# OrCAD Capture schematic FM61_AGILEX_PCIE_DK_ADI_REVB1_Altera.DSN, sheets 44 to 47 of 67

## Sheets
44 MAX10 - USB Blaster II -2: size B
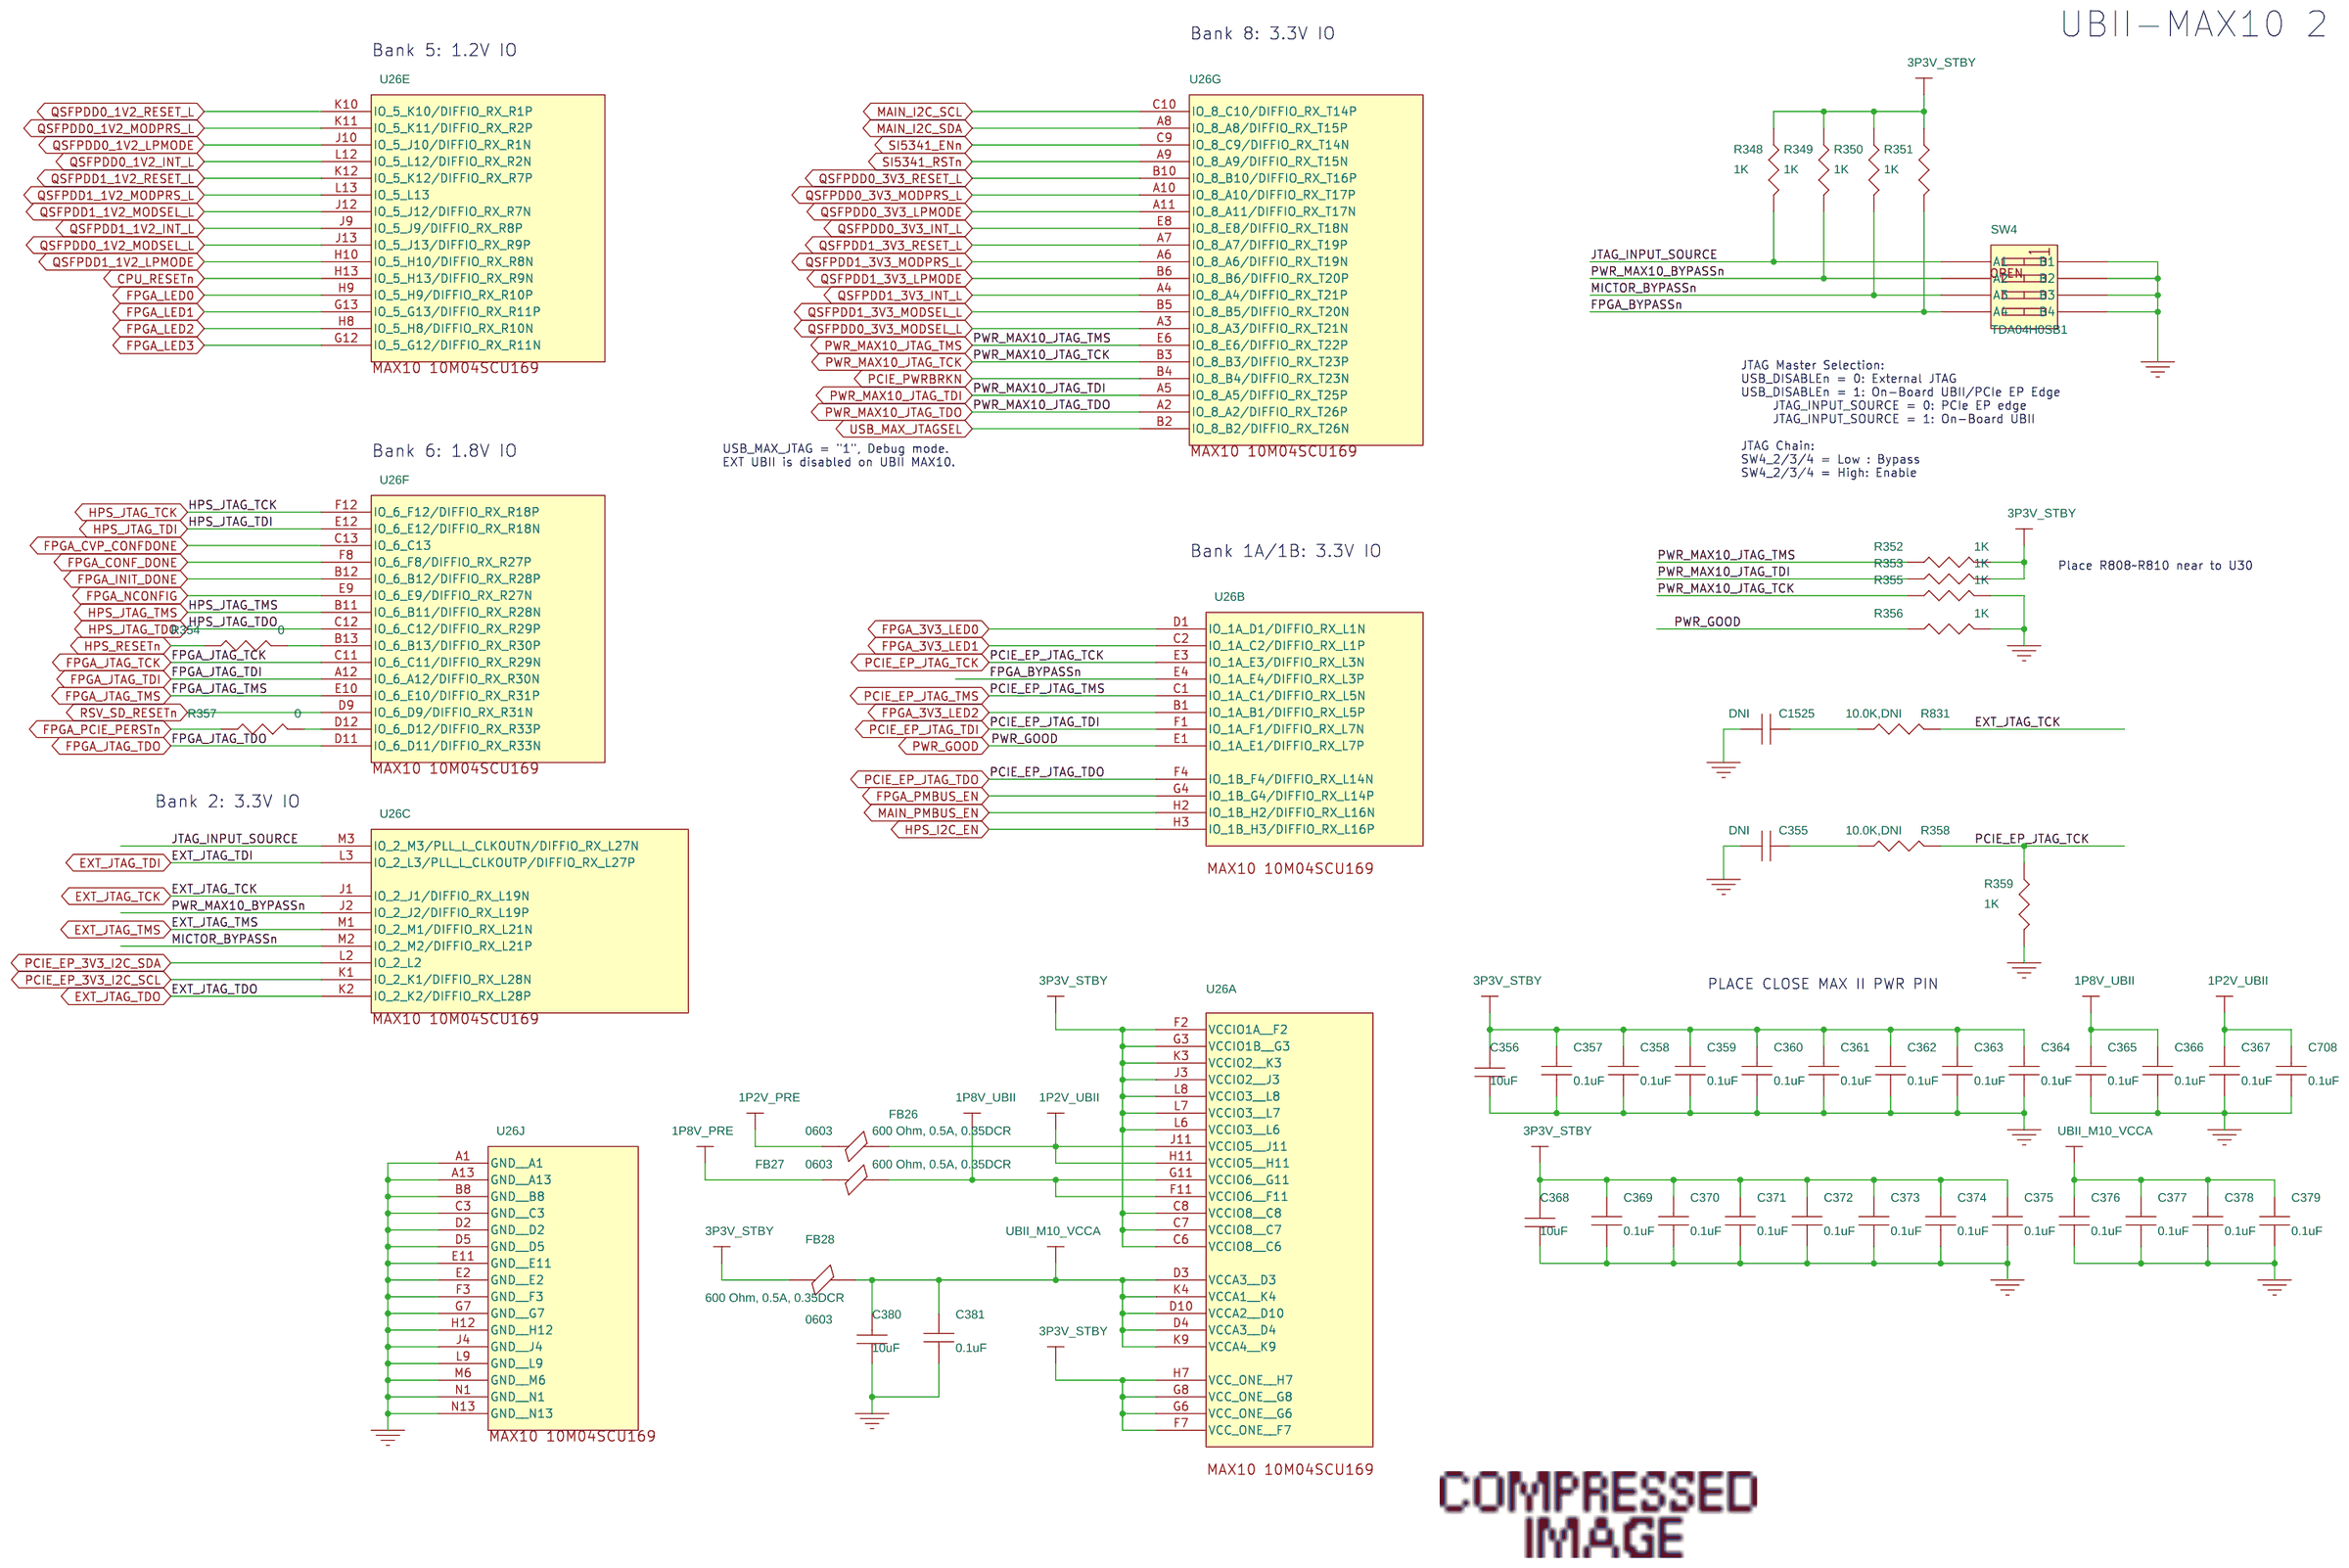
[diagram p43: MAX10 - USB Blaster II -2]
45 PWR - VCCA_PLL: size B
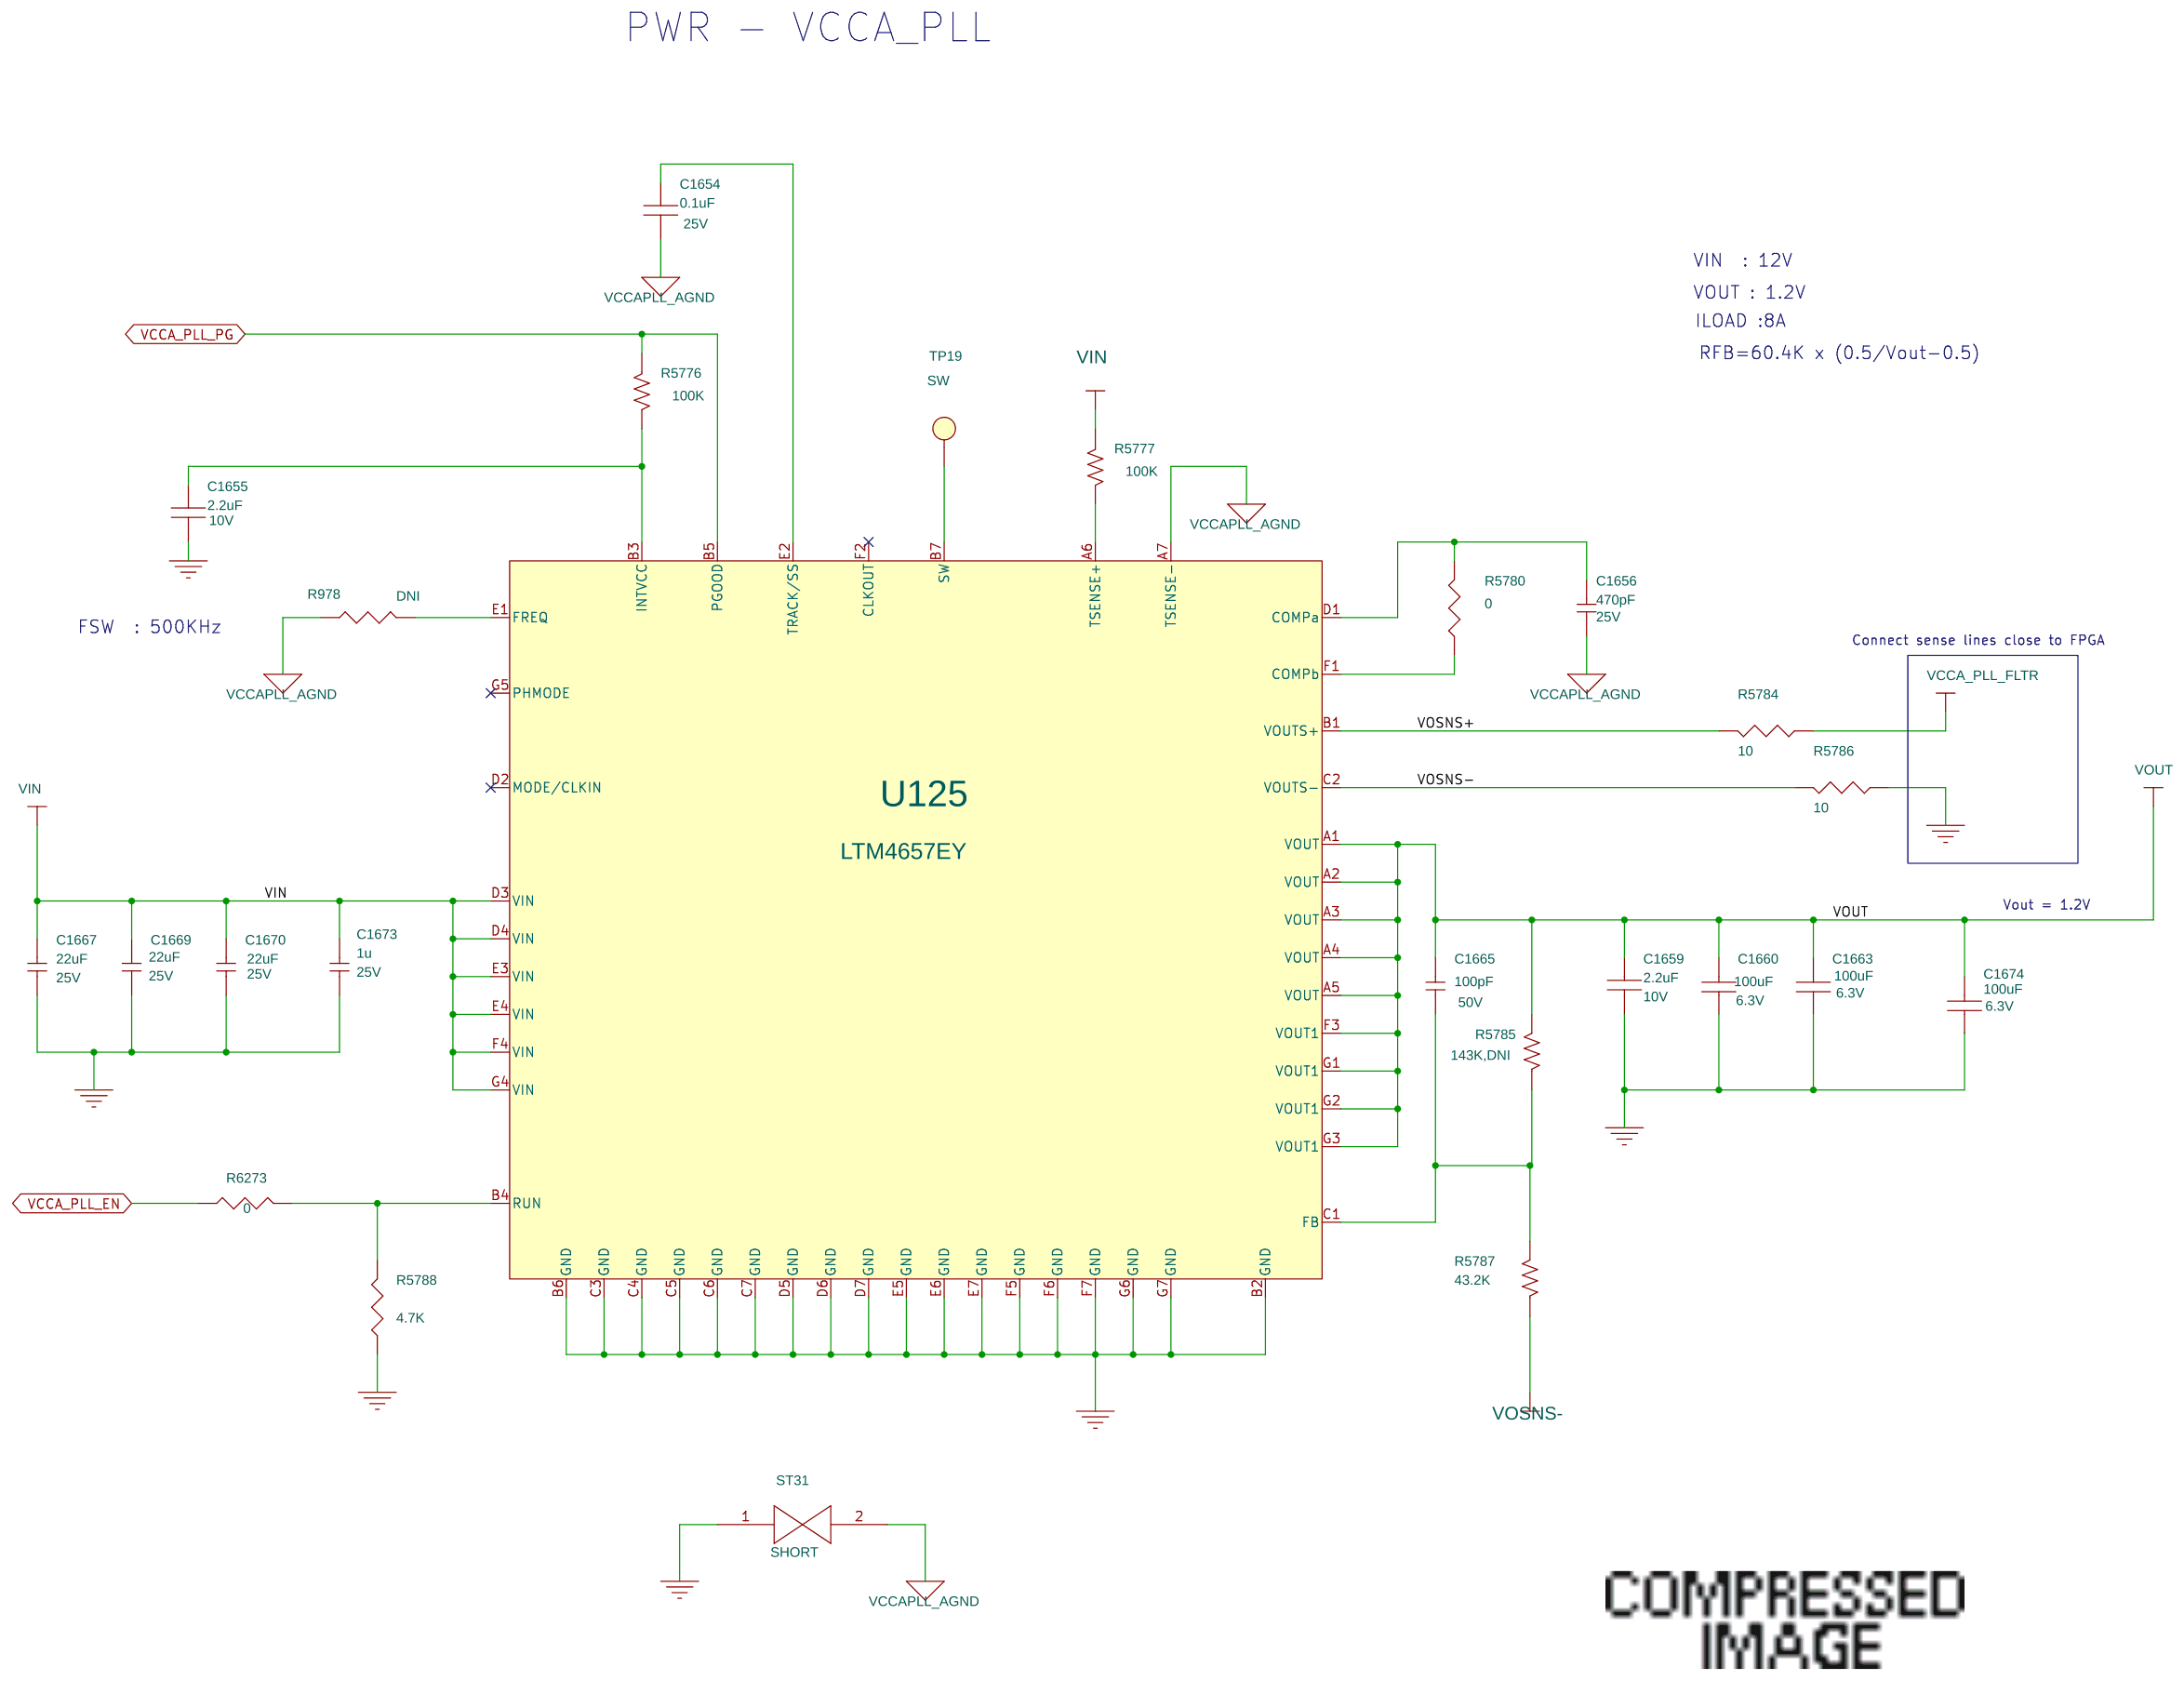
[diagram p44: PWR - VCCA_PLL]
46 MAX10 Power Control -1: size B
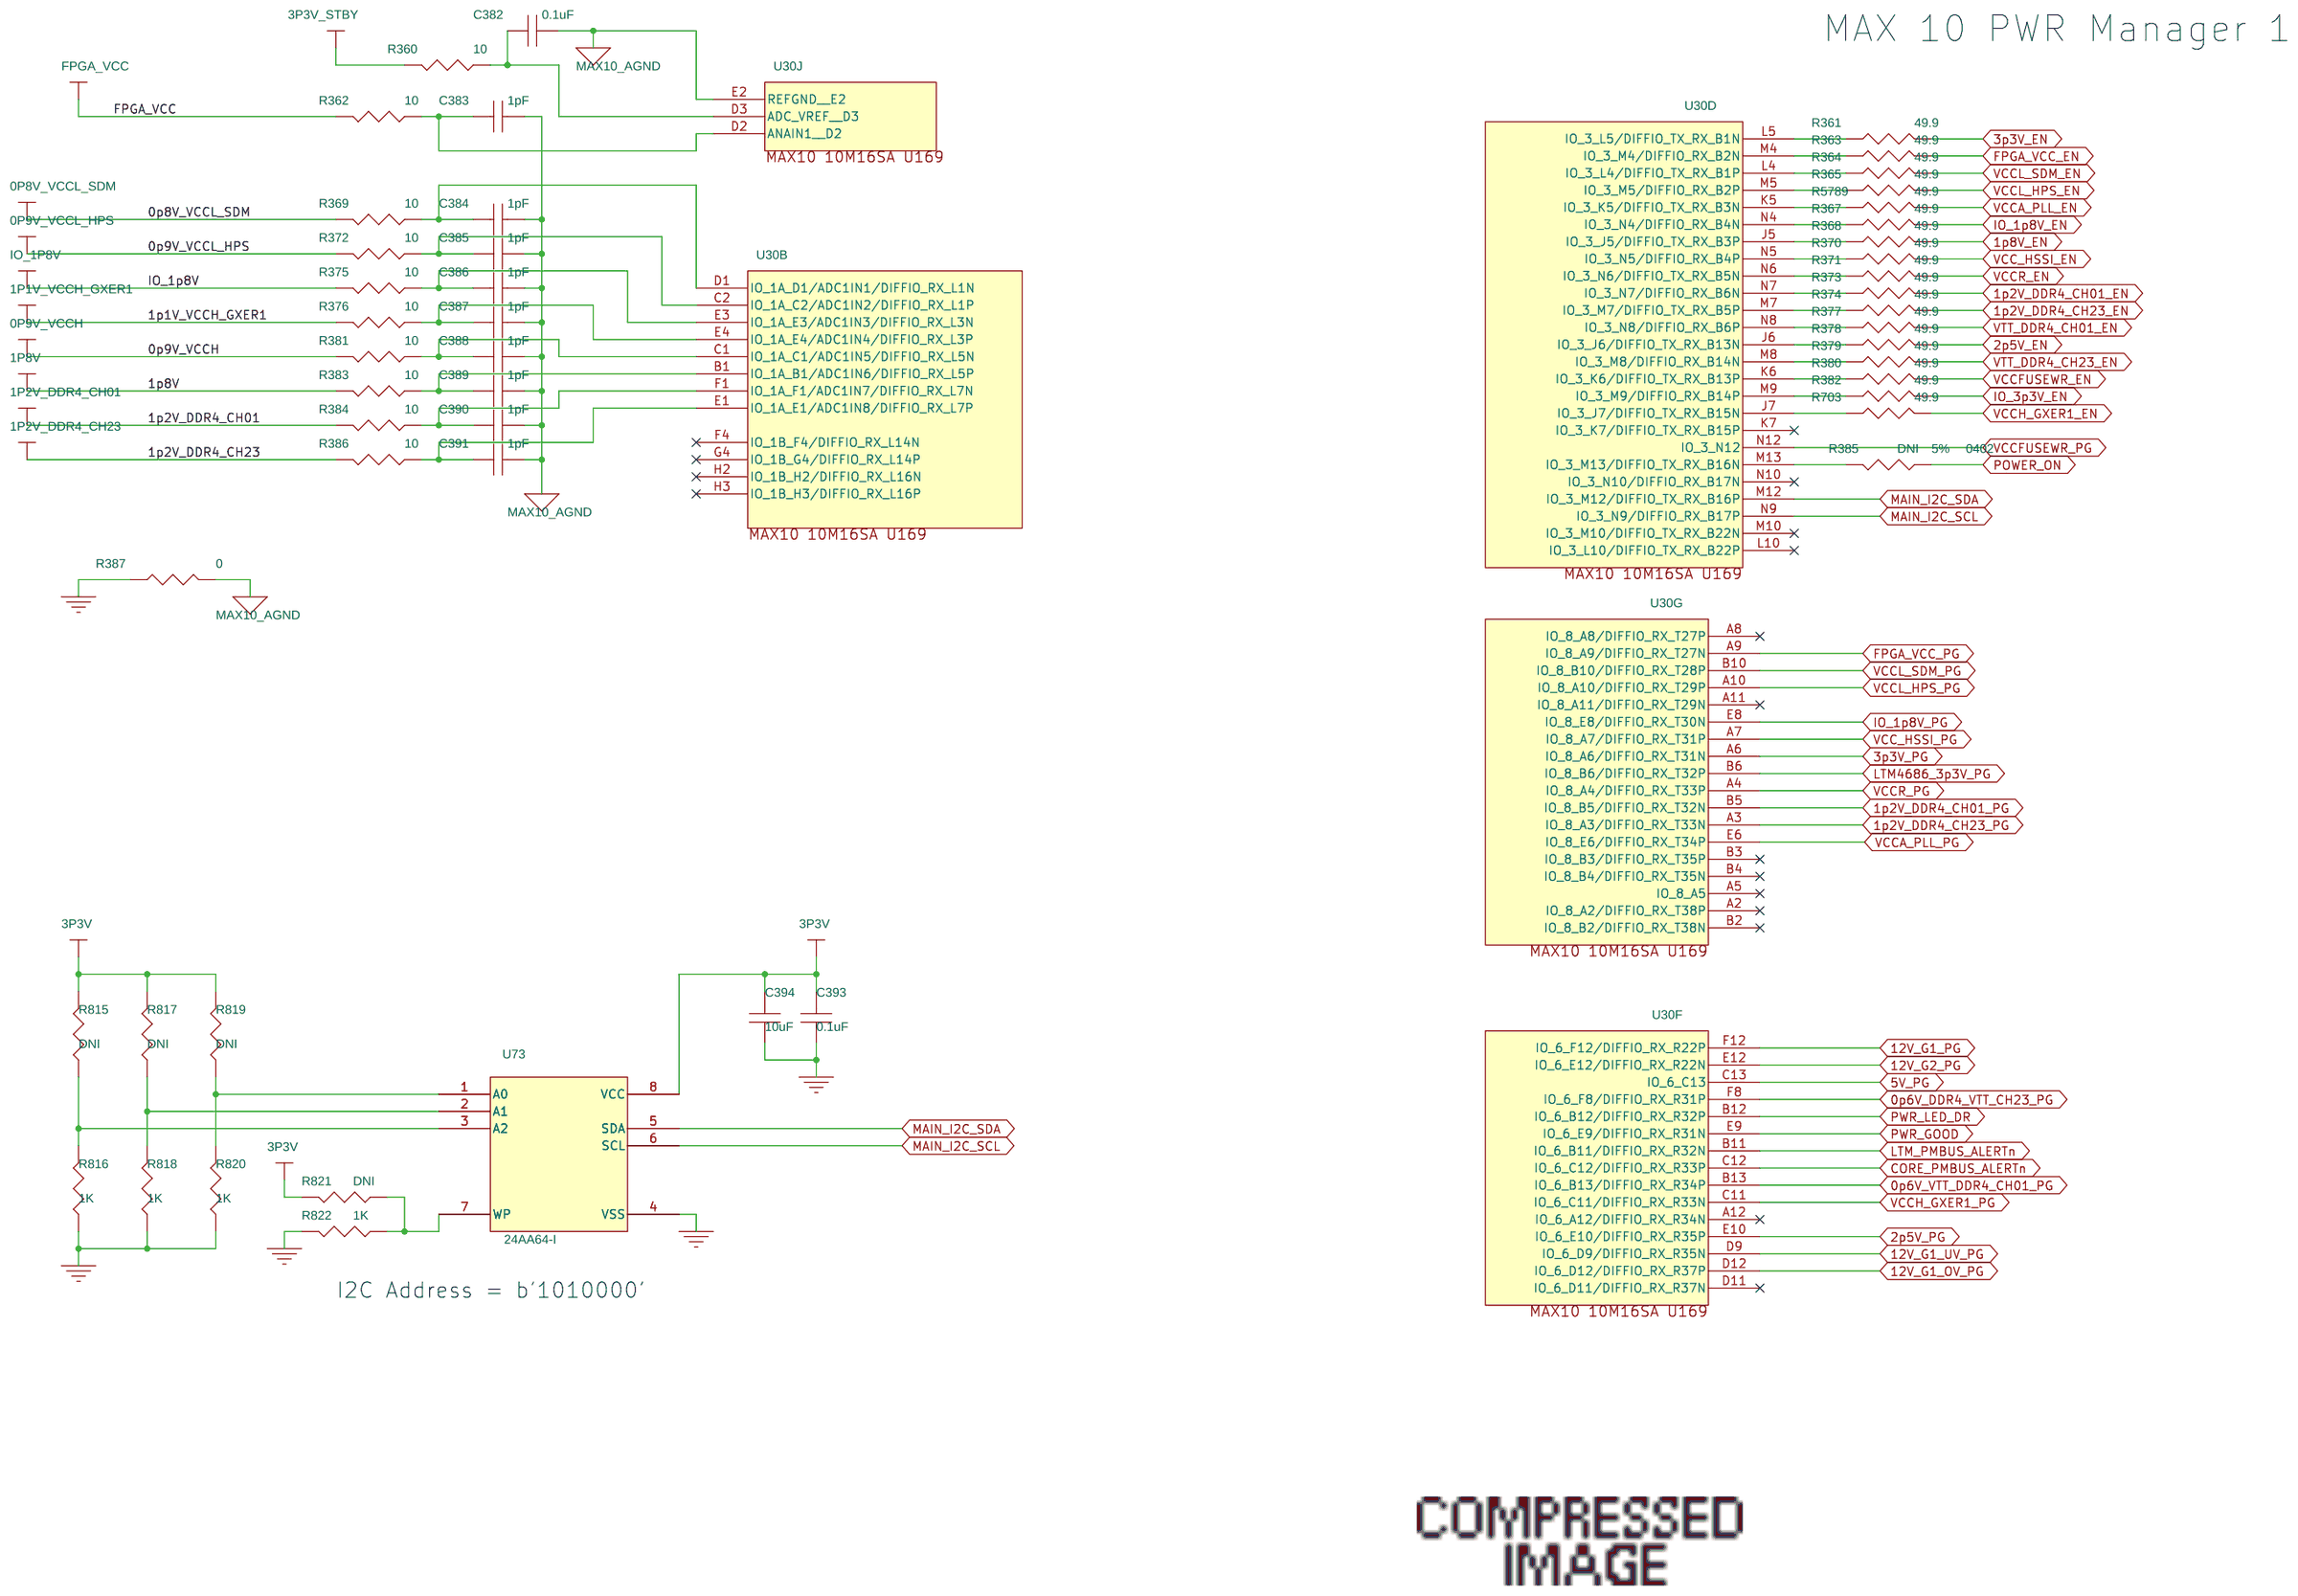
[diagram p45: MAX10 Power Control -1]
47 MAX10 Power Control -2: size B
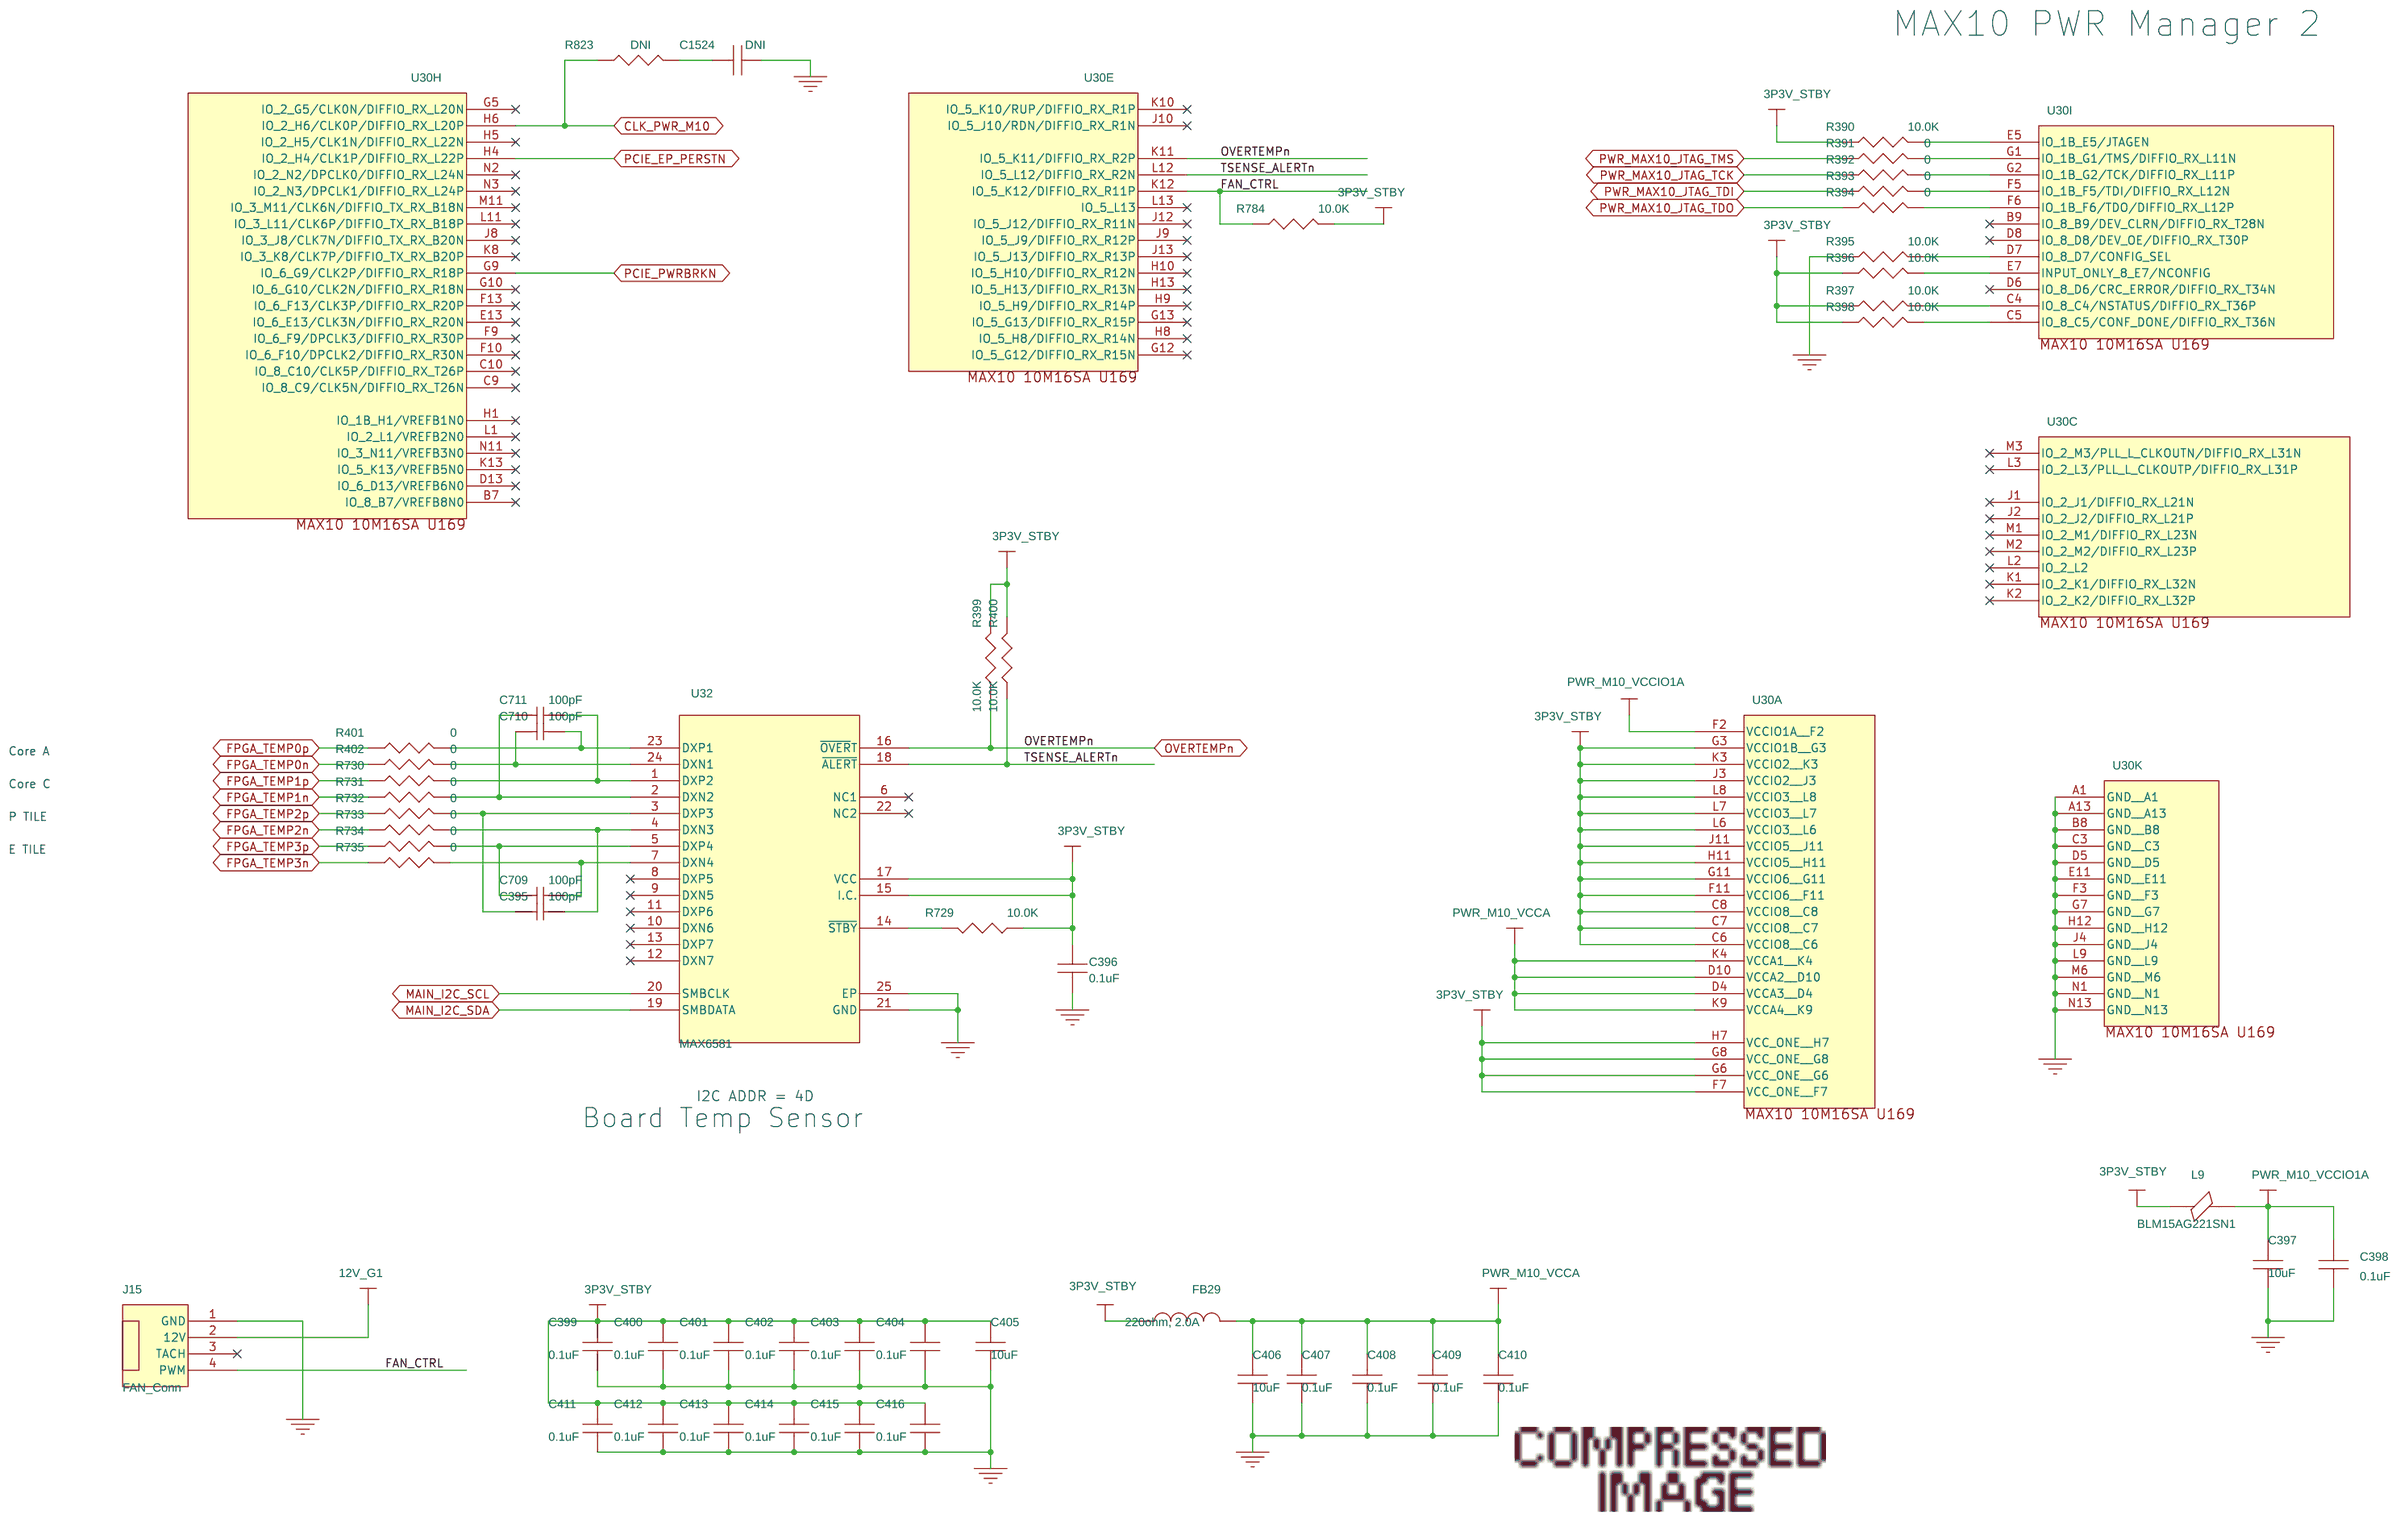
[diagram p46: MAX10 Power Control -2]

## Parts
sheet MAX10 - USB Blaster II -1
U26  10M04SCU169  [BGA169-0R80-11X11]  (sections A,B,C,D,E,F,G,H,I,J)
sheet MAX10 - USB Blaster II -2
C355  DNI  [0402]
C356  10uF  [0603]
C357  0.1uF  [0402]
C358  0.1uF  [0402]
C359  0.1uF  [0402]
C360  0.1uF  [0402]
C361  0.1uF  [0402]
C362  0.1uF  [0402]
C363  0.1uF  [0402]
C364  0.1uF  [0402]
C365  0.1uF  [0402]
C366  0.1uF  [0402]
C367  0.1uF  [0402]
C368  10uF  [0603]
C369  0.1uF  [0402]
C370  0.1uF  [0402]
C371  0.1uF  [0402]
C372  0.1uF  [0402]
C373  0.1uF  [0402]
C374  0.1uF  [0402]
C375  0.1uF  [0402]
C376  0.1uF  [0402]
C377  0.1uF  [0402]
C378  0.1uF  [0402]
C379  0.1uF  [0402]
C380  10uF  [0603]
C381  0.1uF  [0402]
C708  0.1uF  [0402]
C1525  DNI  [0402]
FB26  600 Ohm, 0.5A, 0.35DCR  [0603]
FB27  600 Ohm, 0.5A, 0.35DCR  [0603]
FB28  600 Ohm, 0.5A, 0.35DCR  [0603]
R348  1K  [0402]
R349  1K  [0402]
R350  1K  [0402]
R351  1K  [0402]
R352  1K  [0402]
R353  1K  [0402]
R354  0  [0402]
R355  1K  [0402]
R356  1K  [0402]
R357  0  [0402]
R358  10.0K,DNI  [0402]
R359  1K  [0402]
R831  10.0K,DNI  [0402]
SW4  TDA04H0SB1  [DIPSWITCH_SMT_QUAD]
sheet MAX10 Power Control -1
C382  0.1uF  [0402]
C383  1pF  [0402]
C384  1pF  [0402]
C385  1pF  [0402]
C386  1pF  [0402]
C387  1pF  [0402]
C388  1pF  [0402]
C389  1pF  [0402]
C390  1pF  [0402]
C391  1pF  [0402]
C393  0.1uF  [0402]
C394  10uF  [0603]
R360  10  [0402]
R361  49.9  [0402]
R362  10  [0402]
R363  49.9  [0402]
R364  49.9  [0402]
R365  49.9  [0402]
R367  49.9  [0402]
R368  49.9  [0402]
R369  10  [0402]
R370  49.9  [0402]
R371  49.9  [0402]
R372  10  [0402]
R373  49.9  [0402]
R374  49.9  [0402]
R375  10  [0402]
R376  10  [0402]
R377  49.9  [0402]
R378  49.9  [0402]
R379  49.9  [0402]
R380  49.9  [0402]
R381  10  [0402]
R382  49.9  [0402]
R383  10  [0402]
R384  10  [0402]
R385  DNI  [0402]
R386  10  [0402]
R387  0  [0402]
R703  49.9  [0402]
R815  DNI  [0402]
R816  1K  [0402]
R817  DNI  [0402]
R818  1K  [0402]
R819  DNI  [0402]
R820  1K  [0402]
R821  DNI  [0402]
R822  1K  [0402]
R5789  49.9  [0402]
U30  10M16SA U169_1  [BGA169-0R80-11X11]  (sections A,B,C,D,E,F,G,H,I,J,K)
U73  24AA64-I  [msop8]
sheet MAX10 Power Control -2
C395  100pF  [0402]
C396  0.1uF  [0402]
C397  10uF  [0603]
C398  0.1uF  [0402]
C399  0.1uF  [0402]
C400  0.1uF  [0402]
C401  0.1uF  [0402]
C402  0.1uF  [0402]
C403  0.1uF  [0402]
C404  0.1uF  [0402]
C405  10uF  [0603]
C406  10uF  [0603]
C407  0.1uF  [0402]
C408  0.1uF  [0402]
C409  0.1uF  [0402]
C410  0.1uF  [0402]
C411  0.1uF  [0402]
C412  0.1uF  [0402]
C413  0.1uF  [0402]
C414  0.1uF  [0402]
C415  0.1uF  [0402]
C416  0.1uF  [0402]
C709  100pF  [0402]
C710  100pF  [0402]
C711  100pF  [0402]
C1524  DNI  [0402]
FB29  220ohm, 2.0A  [0805]
J15  FAN_Conn  [Molex_0470533000]
L9  BLM15AG221SN1  [0402]
R390  10.0K  [0402]
R391  0  [0402]
R392  0  [0402]
R393  0  [0402]
R394  0  [0402]
R395  10.0K  [0402]
R396  10.0K  [0402]
R397  10.0K  [0402]
R398  10.0K  [0402]
R399  10.0K  [0402]
R400  10.0K  [0402]
R401  0  [0402]
R402  0  [0402]
R729  10.0K  [0402]
R730  0  [0402]
R731  0  [0402]
R732  0  [0402]
R733  0  [0402]
R734  0  [0402]
R735  0  [0402]
R784  10.0K  [0402]
R823  DNI  [0402]
U32  MAX6581  [24TQFN-EP]
sheet PWR - VCCA_PLL
C1654  0.1uF  [0402]
C1655  2.2uF  [0402]
C1656  470pF  [CAPC1005X60L20L]
C1659  2.2uF  [CC0603N]
C1660  100uF  [1206]
C1663  100uF  [1206]
C1665  100pF  [0402]
C1667  22uF  [1206]
C1669  22uF  [1206]
C1670  22uF  [1206]
C1673  1u  [capc1005x60l20l]
C1674  100uF  [1206]
R978  DNI  [0402]
R5776  100K  [R0402]
R5777  100K  [R0402]
R5780  0  [0402]
R5784  10  [0402]
R5785  143K,DNI  [R0402]
R5786  10  [0402]
R5787  43.2K  [R0402]
R5788  4.7K  [0402]
R6273  0  [0402]
ST31  SHORT  [SHORT]
TP19  TEST PAD  [PADSTYLE1]
U125  LTM4657EY  [LTC-BGA-49-1518]

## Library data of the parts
U26 = 10M04SCU169: IPN: 973665
C355 = CAP: CAPC,Y5V,0402,0.1UF,25V,+80/-20%; Dielectric: Y5V; IPN: K13560-001; Item Num: P03-15057R; Lead Free Status: Yes; Manufacturer: Murata; Manufacturer Part Num: GRM155F51E104ZA01D; Num Pins: 2; Part Class: CAPACITORS; Price: 0.07; RoHS Compliant: Yes; Tolerance: 10%
C356 C368 C380 C394 C397 C405 C406 = CAP: CAP CER 10UF 6.3V X6S 0603; AGILE_LINK: http://sj-agile9app/Agile/PLMServlet?action=OpenEmailObject&classid=10000&objid=257560276; IPN: K19402-001; Item Num: P03-17964R; LIFECYCLE_PHASE: Active; Lead Free Status: Not Lead Free; MFR_LIFECYCLE: Active; Manufacturer: TDK; Manufacturer Part Num: C1608X6S0J106M080AC; Num Pins: 2; PART_SUBCLASS: CAPACITORS; RATED_VOLTAGE: 6.3V; RoHS Compliant: RoHS Compliant; TOLERANCE: 20%; Temperature Coefficient: X6S
C357-C367 C369-C379 C381 C708 = CAP: CAPC,Y5V,0402,0.1UF,25V,+80/-20%; Dielectric: Y5V; IPN: K13560-001; Item Num: P03-15057R; LIFECYCLE_PHASE: Active; Lead Free Status: Lead Free; MFR_LIFECYCLE: Active; Manufacturer: Murata; Manufacturer Part Num: GRM155F51E104ZA01D; Num Pins: 2; PART_SUBCLASS: CAPACITORS; Part Class: CAPACITORS; RATED_VOLTAGE: 25V; RoHS Compliant: RoHS Compliant; Tolerance: +80%/-20%
C1524 C1525 = CAP: CAPC,Y5V,0402,0.1UF,25V,+80/-20%; Dielectric: Y5V; IPN: K13560-001; Item Num: P03-15057R; Lead Free Status: Yes; Manufacturer: Murata; Manufacturer Part Num: GRM155F51E104ZA01D; Num Pins: 2; Part Class: CAPACITORS; Price: 0.07; RATED_VOLTAGE: 25V; RoHS Compliant: Yes; Tolerance: 10%
FB26-FB28 = BEAD_FERRITE_SM: FERRITE BEAD 600 OHM, 0.5A, 0.35 DCR, 0603 1LN; IPN: G73133-001; Item Num: P04-17224R; LIFECYCLE_PHASE: Active; MFR_LIFECYCLE: Active; Manufacturer: Murata; Manufacturer Part Num: BLM18EG601SN1D; Num Pins: 2; Part Class: Inductors; RoHS Compliant: Yes
R348-R353 R355 R356 R359 R815-R822 = RESISTOR: RES,1.00K OHMS,1.0%,1/16W,0402; IPN: G60609-021; Item Num: P02-11372R; Lead Free Status: No; Manufacturer: Panasonic; Manufacturer Part Num: ERJ-2RKF1001X; Num Pins: 2; Part Class: Resistors
R354 R357 R387 R391-R394 R401 R402 R730-R735 = RESISTOR: RES ZERO OHM 1/16W 5% 0402 SMD; Altera Part No.: P02-14020R; IPN: H30887-001; Item Num: P02-14020R; Lead Free Status: No; Manufacturer: Panasonic; Manufacturer Part Num: ERJ-2GE0R00X; Num Pins: 2; Part Class: RESISTORS; RoHS Compliant: Yes; Tolerance: 5%
R358 R831 = RESISTOR: RES,10.0K OHMS,1.0%,1/16W, 0402; IPN: A93548-034; Item Num: P02-11364R; Lead Free Status: No; Manufacturer: Panasonic; Manufacturer Part Num: ERJ-2RKF1002X; Num Pins: 2; Part Class: Resistors; Price: 0; RoHS Compliant: Yes
SW4 = SPST4: SWITCHES - 4 POS, 8 PIN, Ultra-mini SMT Half-pitch Slider DIP Switch; IPN: K15518-001; Item Num: P11-24098R; Lead Free Status: Yes; Manufacturer: C & K Components/ITT Industries; Num Pins: 8; Part Class: Switches; Price: 0; RoHS Compliant: Yes; Supplier: 8
C382 C396 = CAP: CAPC,Y5V,0402,0.1UF,25V,+80/-20%; AGILE_LINK: http://sj-agile9app/Agile/PLMServlet?action=OpenEmailObject&classid=10000&objid=213459527; IPN: K13560-001; Item Num: P03-15057R; LIFECYCLE_PHASE: Active; Lead Free Status: Lead Free; MFR_LIFECYCLE: Active; Manufacturer: Murata; Manufacturer Part Num: GRM155F51E104ZA01D; Num Pins: 2; PART_SUBCLASS: CAPACITORS; Part Class: CAPACITORS; RATED_VOLTAGE: 25V; RoHS Compliant: RoHS Compliant; TOLERANCE: +80%/-20%
C383-C391 = CAP: CAP - CERAMIC, 1PF, +/-0.25PF,  50V, 0402, C0G; AGILE_LINK: http://sj-agile9app/Agile/PLMServlet?action=OpenEmailObject&classid=10000&objid=218192110; IPN: K13552-001; IPN No: K13552-001; Item Num: P03-15104R; LIFECYCLE_PHASE: Active; MFR_LIFECYCLE: Active; Manufacturer: Murata; Manufacturer Part Num: GJM1555C1H1R0CB01D; Num Pins: 2; PART_SUBCLASS: CAPACITORS; RATED_VOLTAGE: 50V; RoHS Compliant: RoHS Compliant
C393 = CAP: CAP CER 0.1UF 25V 20% X7R 0402; IPN: K13660-001; Item Num: P03-17618R; LIFECYCLE_PHASE: Active; Lead Free Status: Lead Free; Manufacturer: TDK Electronics; Manufacturer Part Num: C1005X7R1E104M; Num Pins: 2; Part Class: CAPACITORS; Price: 0; RoHS Compliant: RoHS Compliant
R360 R362 R369 R372 R375 R376 R381 R383 R384 R386 = RES_10_OHM_1.0%_1_16W_0402: RES, 10 OHMS, 1.0%, 1/10W, 0402; IPN: A80345-001; TOLERANCE: 1%
R361 R363-R365 R367 R368 R370 R371 R373 R374 R377-R380 R382 R703 R823 R5789 = RESISTOR: RES, 49.9 OHMS, 1%, 1/16W, 0402; IPN: K16545-001; Item Num: P02-14101R; Lead Free Status: Yes; Manufacturer: NIC Components Corp.; Manufacturer Part Num: NRC04F49R9TRF; Num Pins: 2; Part Class: Resistors; Price: 0
R385 = RESISTOR: RES ZERO OHM 1/16W 5% 0402 SMD; Altera Part No.: P02-14020R; IPN: H30887-001; Item Num: P02-14020R; Lead Free Status: No; Manufacturer: Panasonic; Manufacturer Part Num: ERJ-2GE0R00X; Num Pins: 2; Part Class: RESISTORS; Price: 0; RoHS Compliant: Yes; Tolerance: 5%
U30 = 10M16SA_U169_1: IC - MAX 10 10M16 SINGLE-SUPPLY DEVICE, SINGLE ADC BLOCK, 169-PIN UBGA, 3.0 OR 3.3V SUPPLY; IPN: 967765
U73 = 24AA64-I: IC - 64KBIT I2C SERIAL EEPROM; IPN: K41311-001; Item Num: P01-17386R; Manufacturer: Microchip Technology Inc.; Manufacturer Part Num: 24AA64-I/MS; Num Pins: 8; Part Class: ICS
C395 C709-C711 = Cap,_NP,_0402: CAPC,C0G,0402,100.000PF,50.000V,+/-5%; IPN: A36095-026; Item Num: P03-11677R; Manufacturer: Murata; Manufacturer Part Num: UMK105CG101JV-F; RATED_VOLTAGE: 50V
C398-C404 C407-C416 = CAP: CAPC,Y5V,0402,0.1UF,25V,+80/-20%; Dielectric: Y5V; IPN: K13560-001; Item Num: P03-15057R; LIFECYCLE_PHASE: Active; Lead Free Status: Lead Free; MFR_LIFECYCLE: Active; Manufacturer: Murata; Manufacturer Part Num: GRM155F51E104ZA01D; Num Pins: 2; PART_SUBCLASS: CAPACITORS; Part Class: CAPACITORS; RATED_VOLTAGE: 25V; RoHS Compliant: RoHS Compliant; TOLERANCE: +80%/-20%
FB29 = INDUCTOR: IND - FERRITE BEAD 220 OHM 2.0A 0805; IPN: K14422-001; Item Num: P04-17105R; Lead Free Status: No; Manufacturer: Wurth Elektronik; Manufacturer Part Num: 742792022; Mfr Code: STED; Num Pins: 2; Part Class: Inductors; Price: 0.11; RoHS Compliant: Yes
J15 = FAN_Conn_0: 4 POSITIONS HEADER, UNSHROUDED CONNECTOR 0.100" (2.54MM) THROUGH HOLE TIN; IPN: K21517-001; Item Num: P23-38775R; Manufacturer: Molex; Manufacturer Name: Molex; Manufacturer Part Num: 0470533000
L9 = IND_Ferrite_0402_300mA_220: IPN: K14401-001
R390 R395-R400 R729 R784 = RESISTOR: RES,10.0K OHMS,1.0%,1/16W, 0402; AGILE_LINK: http://sj-agile9app/Agile/PLMServlet?action=OpenEmailObject&classid=10000&objid=146548997; IPN: A93548-034; Item Num: P02-11364R; LIFECYCLE_PHASE: Active; Lead Free Status: No; MFR_LIFECYCLE: Active; Manufacturer: Panasonic; Manufacturer Part Num: ERJ-2RKF1002X; Num Pins: 2; PART_SUBCLASS: RESISTORS; POWER: 1/16W; RoHS Compliant: Yes; TOLERANCE: +/-1%
U32 = MAX6581_0: ICS - ±1°C ACCURATE 8-CHANNEL TEMPERATURE SENSOR; IPN: G97129-001; Item Num: P01-18157R; Manufacturer: Maxim; Manufacturer Part Num: MAX6581TG9A+
C1654 = CAP: CAP CER 0.1UF 25V X6S 0402; Dielectric: X6S; IPN: K19434-001; IPN No: K19434-001; Item Num: P03-17989R; LIFECYCLE_PHASE: Active; Lead Free Status: Lead Free; Manufacturer: Murata; Manufacturer Part Num: GRM155C81E104KA12D; Num Pins: 2; Part Class: CAPACITORS; RATED_VOLTAGE: 25V; RoHS Compliant: RoHS Compliant; Tolerance: 10%
C1655 = CAP: CAP CER 2.2UF 10V X6S 0402; CAPACITANCE: 0.1uF; Dielectric: X6S; IPN: H90637-001; IPN No: H90637-001; Item Num: P03-17966R; LIFECYCLE_PHASE: Active; Lead Free Status: Lead Free; Manufacturer: Murata; Manufacturer Part Num: GRM155C81A225KE44D; Num Pins: 2; Part Class: CAPACITORS; RATED_VOLTAGE: 10V; RoHS Compliant: RoHS Compliant; Tolerance: 10%
C1656 = Cap,_NP,_0402: CAPC,X7R,0402,470PF,25V,+/- 10%; Agile Part Number: P03-17965R; IPN: K19444-001; Manufacturer: Murata; Manufacturer Part Num: C0402C471K3RACTU; Package: 0402; Part Number: C0402C471K3RACTU; Voltage: 25V
C1659 = CAP: CAP, CERAMIC, 2.2UF, 10%, 10VDC, X5R, 0603; CLASS: DISCRETE; Dielectric Type: X7R; FPLIST: CC0603N,CC0603L,CC0603M; IPN: K13568-001; Inventory Qty: 15202; Manufacturer: kemet; Manufacturer PN: GRM188R61A225KE34x; Manufacturer Part Num: GRM188R61A225KE34x; PART_NUMBER: 150-3503; Package Size: 0603; Rated Voltage: 10V; Tolerance: 20%; Voltage: 10V
C1660 C1663 C1674 = CAP: CAP CER 100UF 6.3V X6T 1206; AGILE_LINK: http://sj-agile9app/Agile/PLMServlet?action=OpenEmailObject&classid=10000&objid=257560276; IPN: H65271-004; Item Num: P03-18002R; LIFECYCLE_PHASE: Active; Lead Free Status: Lead Free; MFR_LIFECYCLE: Active; Manufacturer: Murata; Manufacturer Part Num: GRM31CD80J107ME39L; Num Pins: 2; PART_SUBCLASS: CAPACITORS; RATED_VOLTAGE: 6.3V; RoHS Compliant: RoHS Compliant; TOLERANCE: 20%; Temperature Coefficient: X6T; Voltage: 6.3V
C1665 = Cap,_NP,_0402: CAPC,C0G,0402,100.000PF,50.000V,+/-5%; Agile Part Number: P03-11677R; Dielectric: NPO; IPN: A36095-026; Item Num: P03-11677R; Manufacturer: Panasonic; Manufacturer Part Num: UMK105CG101JV-F; Part Number: CL05C101JB5NNNC; TOLERANCE: ±5%; Voltage: 50V
C1667 C1669 C1670 = Cap,_NP,_1206: CAP - CER, 22UF, 25V, 10%, X5R, 1206; IPN: K28232-001; Item Num: P03-17640R; Manufacturer: Murata; Manufacturer Part Num: GRM31CR61E226KE15L; Voltage: 25V
C1673 = Cap,_NP,_0402: CAPC,X6S,0402,1.00UF,25V,+/- 10%; Agile Part Number: 11606; Dielectric: X5R/X6S; IPN: H81594-001; Manufacturer: Murata; Manufacturer Part Num: GRM155C81E105KE11D; Package: 0402; Part Number: GRM155C81E105KE11D; Structure: MLCC; Voltage: 25V
R978 = RESISTOR: RES,332K OHMS,1.0%,1/16W, 0402; AGILE_LINK: http://sj-agile9app/Agile/PLMServlet?action=OpenEmailObject&classid=10000&objid=146548997; IPN: D40152-001; Item Num: A93548-501; LIFECYCLE_PHASE: Active; Lead Free Status: No; MFR_LIFECYCLE: Active; Manufacturer: Yageo; Manufacturer Part Num: RC0402FR-07332KL; Num Pins: 2; PART_SUBCLASS: RESISTORS; POWER: 1/16W; RESISTANCE: 332K; RoHS Compliant: Yes; TOLERANCE: 1%
R5776 R5777 = Resistor,_0402: RES,100K OHMS,1.0%,1/16W,0402; IPN: E86804-001; Item Num: P02-11386R; Manufacturer: Panasonic; Manufacturer Part Num: ERJ-2RKF1003X; POWER: 1/16W; TOLERANCE: +/-1%
R5780 = RESISTOR: RES ZERO OHM 1/16W 5% 0402 SMD; Altera Part No.: P02-14020R; IPN: H30887-001; Item Num: P02-14020R; LIFECYCLE_PHASE: Active; Lead Free Status: No; MFR_LIFECYCLE: Active; Manufacturer: Panasonic; Manufacturer Part Num: ERJ-2GE0R00X; Num Pins: 2; PART_SUBCLASS: RESISTORS; POWER: 1/16W; Part Class: RESISTORS; RoHS Compliant: RoHS Compliant; Tolerance: +/-5%
R5784 R5786 = RESISTOR_0402: RES 10 OHM 1/16W 5% 0402 SMD; IPN: K48300-001; Item Num: K48300-001; Lead Free Status: No; Manufacturer: Panasonic; Manufacturer Part Num: ERJ-2GEJ100X; Num Pins: 2; Part Class: Resistors; Price: 0; RoHS Compliant: Yes
R5785 = Resistor,_0402: RES - 143K OHMS, 1.0%, 1/16W, 0402; IPN: K16192-001; Item Num: P02-16411R; Manufacturer: Vishay; Manufacturer Part Num: CRCW0402143KFKxx
R5787 = Resistor,_0402: RES - 43.2K OHMS, 1.0%, 1/16W, 0402; IPN: G21796-361; Item Num: G21796-361; Manufacturer: Yageo; Manufacturer Part Num: RC0402FR-0743K2P
R5788 = RESISTOR: RES 4.7K OHM 1/16W 5% 0402 SMD; IPN: H30885-001; Item Num: P02-14032R; Lead Free Status: No; Manufacturer: Panasonic; Manufacturer Part Num: ERJ-2GEJ472X; Manufacturer's Part No.: ERJ-2GEJ472X; Num Pins: 2; Part Class: RESISTORS; Price: 0; RoHS Compliant: Yes
R6273 = RESISTOR: RES ZERO OHM 1/16W 5% 0402 SMD; IPN: H30887-001; Item Num: P02-14020R; Lead Free Status: No; Manufacturer: Panasonic; Manufacturer Part Num: ERJ-2GE0R00X; Num Pins: 2; Part Class: RESISTORS; RoHS Compliant: Yes; Tolerance: 5%
ST31 = SHORT
TP19 = PAD_STYLE_C: TESTPOINT, PCB COPPER FEATURE; CLASS: IO; FPLIST: PADSTYLE1,PADSTYLE2,PADSTYLE3,PADSTYLE4,PADSTYLE5,PADSTYLE6,PADSTYLE7,PADSTYLE8; Manufacturer: N/A; Manufacturer PN: N/A; Manufacturer Part Num: N/A; PART_FIELD_01: SW; PART_NUMBER: PCBPADS-1
U125 = LTM4657-BGA_0: IC,Step-Down uModule Reg,BGA-49; CLASS: IC; IPN: M29833-001; Inventory Qty: 0; Item Num: M29833-001; Manufacturer: ANALOG DEVICES; Manufacturer PN: LTM4657EY#PBF; Manufacturer Part Num: LTM4657EY#PBF; PART_NUMBER: LTM4657EY#PBF; Package Type: BGA-49

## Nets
5V_PG: U30.C13(IO_6) ; also on sheet 49
12V_G1: J15.2(12V) ; also on sheet 9 12 15 18 48 51 52 53 58
12V_G1_OV_PG: U30.D12(IO_6_D12/DIFFIO_RX_R37P) ; also on sheet 48
12V_G1_PG: U30.F12(IO_6_F12/DIFFIO_RX_R22P) ; also on sheet 48
12V_G1_UV_PG: U30.D9(IO_6_D9/DIFFIO_RX_R35N) ; also on sheet 48
12V_G2: C1667.2 C1669.2 C1670.2 C1673.1 R5777.1 U125.D3(VIN) U125.D4(VIN) U125.E3(VIN) U125.E4(VIN) U125.F4(VIN) U125.G4(VIN) ; also on sheet 48 49 50 54 55 57 60 61 63 64
12V_G2_PG: U30.E12(IO_6_E12/DIFFIO_RX_R22N) ; also on sheet 48
GND: C355.2 C356.1 C357.2 C358.2 C359.2 C360.2 C361.2 C362.2 C363.2 C364.2 C365.2 C366.2 C367.2 C368.1 C369.2 C370.2 C371.2 C372.2 C373.2 C374.2 C375.2 C376.2 C377.2 C378.2 C379.2 C380.1 C381.2 C393.1 C394.1 C396.2 C397.1 C398.1 C399.1 C400.1 C401.1 C402.1 C403.1 C404.1 C405.1 C406.1 C407.1 C408.1 C409.1 C410.1 C411.1 C412.1 C413.1 C414.1 C415.1 C416.1 C708.2 C1524.1 C1525.2 C1655.2 C1659.2 C1660.1 C1663.1 C1667.1 C1669.1 C1670.1 C1673.2 C1674.1 J15.1(GND) R355.1 R356.1 R359.1 R387.2 R395.1 R816.2 R818.2 R820.2 R822.1 R5786.1 R5788.1 ST31.1 SW4.5(B4) SW4.6(B3) SW4.7(B2) SW4.8(B1) U26.A1(GND_) U26.A13(GND_) U26.B8(GND_) U26.C3(GND_) U26.D2(GND_) U26.D5(GND_) U26.E2(GND_) U26.E11(GND_) U26.F3(GND_) U26.G7(GND_) U26.H12(GND_) U26.J4(GND_) U26.L9(GND_) U26.M6(GND_) U26.N1(GND_) U26.N13(GND_) U30.A1(GND_) U30.A13(GND_) U30.B8(GND_) U30.C3(GND_) U30.D5(GND_) U30.E11(GND_) U30.F3(GND_) U30.G7(GND_) U30.H12(GND_) U30.J4(GND_) U30.L9(GND_) U30.M6(GND_) U30.N1(GND_) U30.N13(GND_) U32.21(GND) U32.25(EP) U73.4(VSS) U125.B2(GND) U125.B6(GND) U125.C3(GND) U125.C4(GND) U125.C5(GND) U125.C6(GND) U125.C7(GND) U125.D5(GND) U125.D6(GND) U125.D7(GND) U125.E5(GND) U125.E6(GND) U125.E7(GND) U125.F5(GND) U125.F6(GND) U125.F7(GND) U125.G6(GND) U125.G7(GND) ; also on sheet 9 11 12 13 14 15 17 18 20 21 22 23 24 25 26 28 29 30 31 32 34 35 36 37 38 39 40 41 42 43 48 49 50 51 52 53 54 55 56 57 58 59 60 61 62 63 64 65 66
VCC_HSSI_EN: R370.2 ; also on sheet 58
VCC_HSSI_PG: U30.A7(IO_8_A7/DIFFIO_RX_T31P) ; also on sheet 58
VCCA_PLL: C1659.1 C1660.2 C1663.2 C1665.2 C1674.2 R5785.2 U125.A1(VOUT) U125.A2(VOUT) U125.A3(VOUT) U125.A4(VOUT) U125.A5(VOUT) U125.F3(VOUT1) U125.G1(VOUT1) U125.G2(VOUT1) U125.G3(VOUT1) ; also on sheet 34
VCCA_PLL_EN: R5789.2 R6273.2
VCCA_PLL_FLTR: R5784.1 ; also on sheet 34 65
VCCA_PLL_PG: R5776.1 U30.E6(IO_8_E6/DIFFIO_RX_T34P) U125.B5(PGOOD)
VCCAPLL_AGND: C1654.2 C1656.1 R978.2 ST31.2 U125.A7(TSENSE-)
VCCFUSEWR_EN: R380.2 ; also on sheet 64
VCCFUSEWR_PG: U30.N12(IO_3) ; also on sheet 64
VCCH_GXER1_EN: R703.2 ; also on sheet 64
VCCH_GXER1_PG: U30.C11(IO_6_C11/DIFFIO_RX_R33N) ; also on sheet 64
VCCL_HPS_EN: R365.2 ; also on sheet 56
VCCL_HPS_PG: U30.A10(IO_8_A10/DIFFIO_RX_T29P) ; also on sheet 56
VCCL_SDM_EN: R364.2 ; also on sheet 55
VCCL_SDM_PG: U30.B10(IO_8_B10/DIFFIO_RX_T28P) ; also on sheet 55
VCCR_EN: R371.2 ; also on sheet 59
VCCR_PG: U30.A4(IO_8_A4/DIFFIO_RX_T33P) ; also on sheet 59
0p6V_DDR4_VTT_CH23_PG: U30.F8(IO_6_F8/DIFFIO_RX_R31P) ; also on sheet 62
0p6V_VTT_DDR4_CH01_PG: U30.B13(IO_6_B13/DIFFIO_RX_R34P) ; also on sheet 62
0p8V_VCCL_SDM: R369.2 ; also on sheet 34 55 65
0p9V_VCCH: R381.2 ; also on sheet 34 58 66
0p9V_VCCL_HPS: R372.2 ; also on sheet 34 56 65
1p1V_VCCH_GXER1: R376.2 ; also on sheet 34 64 65
1p2V_DDR4_CH01: R384.2 ; also on sheet 9 12 13 34 40 42 60 62 66
1p2V_DDR4_CH01_EN: R373.2 ; also on sheet 60
1p2V_DDR4_CH01_PG: U30.B5(IO_8_B5/DIFFIO_RX_T32N) ; also on sheet 60
1p2V_DDR4_CH23: R386.2 ; also on sheet 15 16 18 19 25 34 61 62 66
1p2V_DDR4_CH23_EN: R374.2 ; also on sheet 61
1p2V_DDR4_CH23_PG: U30.A3(IO_8_A3/DIFFIO_RX_T33N) ; also on sheet 61
1p2V_PRE: FB26.2 ; also on sheet 41 62
1p2V_UBII: C367.1 C708.1 FB26.1 U26.H11(VCCIO5_) U26.J11(VCCIO5_)
1p8V: R383.2 ; also on sheet 22 34 54 65
1p8V_EN: R368.2 ; also on sheet 54
1p8V_PRE: FB27.2 ; also on sheet 49
1p8V_UBII: C365.1 C366.1 FB27.1 U26.F11(VCCIO6_) U26.G11(VCCIO6_)
2p5V_EN: R378.2 ; also on sheet 63
2p5V_PG: U30.E10(IO_6_E10/DIFFIO_RX_R35P) ; also on sheet 63
3p3V: C393.2 C394.2 R815.1 R817.1 R819.1 R821.1 U73.8(VCC) ; also on sheet 50 51 54 55 56 57 58 59 60 61 62 63 64
3p3V_EN: R361.2 ; also on sheet 50
3p3V_PG: U30.A6(IO_8_A6/DIFFIO_RX_T31N) ; also on sheet 50
3p3V_STBY: C356.2 C357.1 C358.1 C359.1 C360.1 C361.1 C362.1 C363.1 C364.1 C368.2 C369.1 C370.1 C371.1 C372.1 C373.1 C374.1 C375.1 C396.1 C399.2 C400.2 C401.2 C402.2 C403.2 C404.2 C405.2 C411.2 C412.2 C413.2 C414.2 C415.2 C416.2 FB28.2 FB29.1 L9.1 R348.2 R349.2 R350.2 R351.2 R352.1 R353.1 R360.2 R390.1 R396.1 R397.1 R398.1 R399.2 R400.2 R729.1 R784.2 U26.C6(VCCIO8_) U26.C7(VCCIO8_) U26.C8(VCCIO8_) U26.F2(VCCIO1A_) U26.F7(VCC_ONE_) U26.G3(VCCIO1B_) U26.G6(VCC_ONE_) U26.G8(VCC_ONE_) U26.H7(VCC_ONE_) U26.J3(VCCIO2_) U26.K3(VCCIO2_) U26.L6(VCCIO3_) U26.L7(VCCIO3_) U26.L8(VCCIO3_) U30.C6(VCCIO8_) U30.C7(VCCIO8_) U30.C8(VCCIO8_) U30.F7(VCC_ONE_) U30.F11(VCCIO6_) U30.G3(VCCIO1B_) U30.G6(VCC_ONE_) U30.G8(VCC_ONE_) U30.G11(VCCIO6_) U30.H7(VCC_ONE_) U30.H11(VCCIO5_) U30.J3(VCCIO2_) U30.J11(VCCIO5_) U30.K3(VCCIO2_) U30.L6(VCCIO3_) U30.L7(VCCIO3_) U30.L8(VCCIO3_) U32.15(I.C.) U32.17(VCC) ; also on sheet 25 39 41 43 48 49 62
CLK_PWR_M10: R823.1 U30.H6(IO_2_H6/CLK0P/DIFFIO_RX_L20P) ; also on sheet 39
CORE_PMBUS_ALERTn: U30.C12(IO_6_C12/DIFFIO_RX_R33P) ; also on sheet 43 51
CPU_RESETn: U26.H13(IO_5_H13/DIFFIO_RX_R9N) ; also on sheet 13 41
EXT_JTAG_TCK: R831.1 U26.J1(IO_2_J1/DIFFIO_RX_L19N) ; also on sheet 43
EXT_JTAG_TDI: U26.L3(IO_2_L3/PLL_L_CLKOUTP/DIFFIO_RX_L27P) ; also on sheet 43
EXT_JTAG_TDO: U26.K2(IO_2_K2/DIFFIO_RX_L28P) ; also on sheet 43
EXT_JTAG_TMS: U26.M1(IO_2_M1/DIFFIO_RX_L21N) ; also on sheet 43
FAN_CTRL: J15.4(PWM) R784.1 U30.K12(IO_5_K12/DIFFIO_RX_R11P)
FPGA_3V3_LED0: U26.D1(IO_1A_D1/DIFFIO_RX_L1N) ; also on sheet 41
FPGA_3V3_LED1: U26.C2(IO_1A_C2/DIFFIO_RX_L1P) ; also on sheet 41
FPGA_3V3_LED2: U26.B1(IO_1A_B1/DIFFIO_RX_L5P) ; also on sheet 41
FPGA_BYPASSn: R351.1 SW4.4(A4) U26.E4(IO_1A_E4/DIFFIO_RX_L3P)
FPGA_CONF_DONE: U26.F8(IO_6_F8/DIFFIO_RX_R27P) ; also on sheet 26 41
FPGA_CVP_CONFDONE: U26.C13(IO_6) ; also on sheet 26 41
FPGA_INIT_DONE: U26.B12(IO_6_B12/DIFFIO_RX_R28P) ; also on sheet 26
FPGA_JTAG_TCK: U26.C11(IO_6_C11/DIFFIO_RX_R29N) ; also on sheet 26
FPGA_JTAG_TDI: U26.A12(IO_6_A12/DIFFIO_RX_R30N) ; also on sheet 26
FPGA_JTAG_TDO: U26.D11(IO_6_D11/DIFFIO_RX_R33N) ; also on sheet 26
FPGA_JTAG_TMS: U26.E10(IO_6_E10/DIFFIO_RX_R31P) ; also on sheet 26
FPGA_LED0: U26.H9(IO_5_H9/DIFFIO_RX_R10P) ; also on sheet 13
FPGA_LED1: U26.G13(IO_5_G13/DIFFIO_RX_R11P) ; also on sheet 13
FPGA_LED2: U26.H8(IO_5_H8/DIFFIO_RX_R10N) ; also on sheet 13
FPGA_LED3: U26.G12(IO_5_G12/DIFFIO_RX_R11N) ; also on sheet 13
FPGA_NCONFIG: U26.E9(IO_6_E9/DIFFIO_RX_R27N) ; also on sheet 26
FPGA_PCIE_PERSTn: R357.1 ; also on sheet 22
FPGA_PMBUS_EN: U26.G4(IO_1B_G4/DIFFIO_RX_L14P) ; also on sheet 40
FPGA_TEMP0n: R402.2 ; also on sheet 26
FPGA_TEMP0p: R401.2 ; also on sheet 26
FPGA_TEMP1n: R731.2 ; also on sheet 32
FPGA_TEMP1p: R730.2 ; also on sheet 32
FPGA_TEMP2n: R733.2 ; also on sheet 22
FPGA_TEMP2p: R732.2 ; also on sheet 22
FPGA_TEMP3n: R735.2 ; also on sheet 21
FPGA_TEMP3p: R734.2 ; also on sheet 21
FPGA_VCC: R362.2 ; also on sheet 33 52 53 65 66
FPGA_VCC_EN: R363.2 ; also on sheet 51
FPGA_VCC_PG: U30.A9(IO_8_A9/DIFFIO_RX_T27N) ; also on sheet 51
HPS_I2C_EN: U26.H3(IO_1B_H3/DIFFIO_RX_L16P) ; also on sheet 40
HPS_JTAG_TCK: U26.F12(IO_6_F12/DIFFIO_RX_R18P) ; also on sheet 30
HPS_JTAG_TDI: U26.E12(IO_6_E12/DIFFIO_RX_R18N) ; also on sheet 30
HPS_JTAG_TDO: U26.C12(IO_6_C12/DIFFIO_RX_R29P) ; also on sheet 30
HPS_JTAG_TMS: U26.B11(IO_6_B11/DIFFIO_RX_R28N) ; also on sheet 30
HPS_RESETn: R354.1 ; also on sheet 26
IO_1p8V: R375.2 ; also on sheet 26 28 29 30 31 34 38 39 40 57 65
IO_1p8V_EN: R367.2 ; also on sheet 57
IO_1p8V_PG: U30.E8(IO_8_E8/DIFFIO_RX_T30N) ; also on sheet 57
IO_3p3V_EN: R382.2 ; also on sheet 63
JTAG_INPUT_SOURCE: R348.1 SW4.1(A1) U26.M3(IO_2_M3/PLL_L_CLKOUTN/DIFFIO_RX_L27N)
LTM4686_3p3V_PG: U30.B6(IO_8_B6/DIFFIO_RX_T32P) ; also on sheet 54
LTM_PMBUS_ALERTn: U30.B11(IO_6_B11/DIFFIO_RX_R32N) ; also on sheet 43 54 58
MAIN_I2C_SCL: U26.C10(IO_8_C10/DIFFIO_RX_T14P) U30.N9(IO_3_N9/DIFFIO_RX_B17P) U32.20(SMBCLK) U73.6(SCL) ; also on sheet 38 39 40 54
MAIN_I2C_SDA: U26.A8(IO_8_A8/DIFFIO_RX_T15P) U30.M12(IO_3_M12/DIFFIO_TX_RX_B16P) U32.19(SMBDATA) U73.5(SDA) ; also on sheet 38 39 40 54
MAIN_PMBUS_EN: U26.H2(IO_1B_H2/DIFFIO_RX_L16N) ; also on sheet 40
MAX10_AGND: C382.2 C383.2 C384.2 C385.2 C386.2 C387.2 C388.2 C389.2 C390.2 C391.2 R387.1 U30.E2(REFGND_)
MICTOR_BYPASSn: R350.1 SW4.3(A3) U26.M2(IO_2_M2/DIFFIO_RX_L21P)
OVERTEMPn: R399.1 U30.K11(IO_5_K11/DIFFIO_RX_R2P) U32.16(~{OVER}T) ; also on sheet 41
PCIE_EP_3V3_I2C_SCL: U26.K1(IO_2_K1/DIFFIO_RX_L28N) ; also on sheet 25
PCIE_EP_3V3_I2C_SDA: U26.L2(IO_2) ; also on sheet 25
PCIE_EP_JTAG_TCK: R358.1 R359.2 U26.E3(IO_1A_E3/DIFFIO_RX_L3N) ; also on sheet 25
PCIE_EP_JTAG_TDI: U26.F1(IO_1A_F1/DIFFIO_RX_L7N) ; also on sheet 25
PCIE_EP_JTAG_TDO: U26.F4(IO_1B_F4/DIFFIO_RX_L14N) ; also on sheet 25
PCIE_EP_JTAG_TMS: U26.C1(IO_1A_C1/DIFFIO_RX_L5N) ; also on sheet 25
PCIE_EP_PERSTN: U30.H4(IO_2_H4/CLK1P/DIFFIO_RX_L22P) ; also on sheet 25 43
PCIE_PWRBRKN: U26.B4(IO_8_B4/DIFFIO_RX_T23N) U30.G9(IO_6_G9/CLK2P/DIFFIO_RX_R18P) ; also on sheet 25
POWER_ON: R385.2 ; also on sheet 48
PWR_GOOD: R356.2 U26.E1(IO_1A_E1/DIFFIO_RX_L7P) U30.E9(IO_6_E9/DIFFIO_RX_R31N)
PWR_LED_DR: U30.B12(IO_6_B12/DIFFIO_RX_R32P) ; also on sheet 41
PWR_M10_VCCA: C406.2 C407.2 C408.2 C409.2 C410.2 FB29.2 U30.D4(VCCA3_) U30.D10(VCCA2_) U30.K4(VCCA1_) U30.K9(VCCA4_)
PWR_M10_VCCIO1A: C397.2 C398.2 L9.2 U30.F2(VCCIO1A_)
PWR_MAX10_BYPASSn: R349.1 SW4.2(A2) U26.J2(IO_2_J2/DIFFIO_RX_L19P)
PWR_MAX10_JTAG_TCK: R355.2 R392.2 U26.B3(IO_8_B3/DIFFIO_RX_T23P)
PWR_MAX10_JTAG_TDI: R353.2 R393.2 U26.A5(IO_8_A5/DIFFIO_RX_T25P)
PWR_MAX10_JTAG_TDO: R394.2 U26.A2(IO_8_A2/DIFFIO_RX_T26P)
PWR_MAX10_JTAG_TMS: R352.2 R391.2 U26.E6(IO_8_E6/DIFFIO_RX_T22P)
QSFPDD0_1V2_INT_L: U26.L12(IO_5_L12/DIFFIO_RX_R2N) ; also on sheet 13
QSFPDD0_1V2_LPMODE: U26.J10(IO_5_J10/DIFFIO_RX_R1N) ; also on sheet 13
QSFPDD0_1V2_MODPRS_L: U26.K11(IO_5_K11/DIFFIO_RX_R2P) ; also on sheet 13
QSFPDD0_1V2_MODSEL_L: U26.J13(IO_5_J13/DIFFIO_RX_R9P) ; also on sheet 13
QSFPDD0_1V2_RESET_L: U26.K10(IO_5_K10/DIFFIO_RX_R1P) ; also on sheet 13
QSFPDD0_3V3_INT_L: U26.E8(IO_8_E8/DIFFIO_RX_T18N) ; also on sheet 23
QSFPDD0_3V3_LPMODE: U26.A11(IO_8_A11/DIFFIO_RX_T17N) ; also on sheet 23
QSFPDD0_3V3_MODPRS_L: U26.A10(IO_8_A10/DIFFIO_RX_T17P) ; also on sheet 23
QSFPDD0_3V3_MODSEL_L: U26.A3(IO_8_A3/DIFFIO_RX_T21N) ; also on sheet 23
QSFPDD0_3V3_RESET_L: U26.B10(IO_8_B10/DIFFIO_RX_T16P) ; also on sheet 23
QSFPDD1_1V2_INT_L: U26.J9(IO_5_J9/DIFFIO_RX_R8P) ; also on sheet 13
QSFPDD1_1V2_LPMODE: U26.H10(IO_5_H10/DIFFIO_RX_R8N) ; also on sheet 13
QSFPDD1_1V2_MODPRS_L: U26.L13(IO_5) ; also on sheet 13
QSFPDD1_1V2_MODSEL_L: U26.J12(IO_5_J12/DIFFIO_RX_R7N) ; also on sheet 13
QSFPDD1_1V2_RESET_L: U26.K12(IO_5_K12/DIFFIO_RX_R7P) ; also on sheet 13
QSFPDD1_3V3_INT_L: U26.A4(IO_8_A4/DIFFIO_RX_T21P) ; also on sheet 24
QSFPDD1_3V3_LPMODE: U26.B6(IO_8_B6/DIFFIO_RX_T20P) ; also on sheet 24
QSFPDD1_3V3_MODPRS_L: U26.A6(IO_8_A6/DIFFIO_RX_T19N) ; also on sheet 24
QSFPDD1_3V3_MODSEL_L: U26.B5(IO_8_B5/DIFFIO_RX_T20N) ; also on sheet 24
QSFPDD1_3V3_RESET_L: U26.A7(IO_8_A7/DIFFIO_RX_T19P) ; also on sheet 24
RSV_SD_RESETn: U26.D9(IO_6_D9/DIFFIO_RX_R31N) ; also on sheet 27
SI5341_ENn: U26.C9(IO_8_C9/DIFFIO_RX_T14N) ; also on sheet 38 39
SI5341_RSTn: U26.A9(IO_8_A9/DIFFIO_RX_T15N) ; also on sheet 38
TSENSE_ALERTn: R400.1 U30.L12(IO_5_L12/DIFFIO_RX_R2N) U32.18(~{ALERT})
UBII_M10_VCCA: C376.1 C377.1 C378.1 C379.1 C380.2 C381.1 FB28.1 U26.D3(VCCA3_) U26.D4(VCCA3_) U26.D10(VCCA2_) U26.K4(VCCA1_) U26.K9(VCCA4_)
USB_MAX_JTAGSEL: U26.B2(IO_8_B2/DIFFIO_RX_T26N) ; also on sheet 39 43
VOSNS+: R5784.2 U125.B1(VOUTS+)
VOSNS-: R5786.2 R5787.1 U125.C2(VOUTS-)
VTT_DDR4_CH01_EN: R377.2 ; also on sheet 62
VTT_DDR4_CH23_EN: R379.2 ; also on sheet 62
N31093028: C355.1 R358.2
N31872869: C383.1 R362.1 U30.D2(ANAIN1_)
N31872899: C384.1 R369.1 U30.D1(IO_1A_D1/ADC1IN1/DIFFIO_RX_L1N)
N31873008: C385.1 R372.1 U30.C2(IO_1A_C2/ADC1IN2/DIFFIO_RX_L1P)
N31873022: R361.1 U30.L5(IO_3_L5/DIFFIO_TX_RX_B1N)
N31873048: R363.1 U30.M4(IO_3_M4/DIFFIO_RX_B2N)
N31873076: C386.1 R375.1 U30.E3(IO_1A_E3/ADC1IN3/DIFFIO_RX_L3N)
N31873106: R364.1 U30.L4(IO_3_L4/DIFFIO_TX_RX_B1P)
N31873136: R365.1 U30.M5(IO_3_M5/DIFFIO_RX_B2P)
N31873164: C387.1 R376.1 U30.E4(IO_1A_E4/ADC1IN4/DIFFIO_RX_L3P)
N31873212: R367.1 U30.N4(IO_3_N4/DIFFIO_RX_B4N)
N31873240: C388.1 R381.1 U30.C1(IO_1A_C1/ADC1IN5/DIFFIO_RX_L5N)
N31873256: R368.1 U30.J5(IO_3_J5/DIFFIO_TX_RX_B3P)
N31873294: R370.1 U30.N5(IO_3_N5/DIFFIO_RX_B4P)
N31873322: C389.1 R383.1 U30.B1(IO_1A_B1/ADC1IN6/DIFFIO_RX_L5P)
N31873334: R371.1 U30.N6(IO_3_N6/DIFFIO_TX_RX_B5N)
N31873366: C390.1 R384.1 U30.F1(IO_1A_F1/ADC1IN7/DIFFIO_RX_L7N)
N31873370: R373.1 U30.N7(IO_3_N7/DIFFIO_RX_B6N)
N31873414: C391.1 R386.1 U30.E1(IO_1A_E1/ADC1IN8/DIFFIO_RX_L7P)
N31873418: R374.1 U30.M7(IO_3_M7/DIFFIO_TX_RX_B5P)
N31873454: R377.1 U30.N8(IO_3_N8/DIFFIO_RX_B6P)
N31873498: R378.1 U30.J6(IO_3_J6/DIFFIO_TX_RX_B13N)
N31873524: R379.1 U30.M8(IO_3_M8/DIFFIO_RX_B14N)
N31875898: R390.2 U30.E5(IO_1B_E5/JTAGEN)
N31875914: R391.1 U30.G1(IO_1B_G1/TMS/DIFFIO_RX_L11N)
N31875930: R392.1 U30.G2(IO_1B_G2/TCK/DIFFIO_RX_L11P)
N31875950: R393.1 U30.F5(IO_1B_F5/TDI/DIFFIO_RX_L12N)
N31875960: R394.1 U30.F6(IO_1B_F6/TDO/DIFFIO_RX_L12P)
N31875982: R396.2 U30.E7(INPUT_ONLY_8_E7/NCONFIG)
N31876004: R397.2 U30.C4(IO_8_C4/NSTATUS/DIFFIO_RX_T36P)
N31876008: R398.2 U30.C5(IO_8_C5/CONF_DONE/DIFFIO_RX_T36N)
N32052935: C710.1 R401.1 U32.23(DXP1)
N32053041: C710.2 R402.1 U32.24(DXN1)
N32411757: R385.1 U30.M13(IO_3_M13/DIFFIO_TX_RX_B16N)
N32411786: C382.1 R360.1 U30.D3(ADC_VREF_)
N33149453: R395.2 U30.D7(IO_8_D7/CONFIG_SEL)
N36228605: R357.2 U26.D12(IO_6_D12/DIFFIO_RX_R33P)
N36273391: R354.2 U26.B13(IO_6_B13/DIFFIO_RX_R30P)
N36347895: R380.1 U30.K6(IO_3_K6/DIFFIO_TX_RX_B13P)
N36349829: R382.1 U30.M9(IO_3_M9/DIFFIO_RX_B14P)
N36447575: R703.1 U30.J7(IO_3_J7/DIFFIO_TX_RX_B15N)
N36800975: R729.2 U32.14(~{STBY})
N36803165: C711.1 R730.1 U32.1(DXP2)
N36803169: C711.2 R731.1 U32.2(DXN2)
N36803267: C395.2 R732.1 U32.3(DXP3)
N36803284: C395.1 R733.1 U32.4(DXN3)
N36803301: C709.2 R734.1 U32.5(DXP4)
N36803305: C709.1 R735.1 U32.7(DXN4)
N37820590: R815.2 R816.1 U73.3(A2)
N37820593: R817.2 R818.1 U73.2(A1)
N37820596: R819.2 R820.1 U73.1(A0)
N37820939: R821.2 R822.2 U73.7(WP)
N37847663: C1524.2 R823.2
N37926941: C1525.1 R831.2
N39028460: C1654.1 U125.E2(TRACK/SS)
N39028581: C1655.1 R5776.2 U125.B3(INTVCC)
N39028605: TP19.1 U125.B7(SW)
N39028640: R5777.2 U125.A6(TSENSE+)
N39028644: C1656.2 R5780.1 U125.D1(COMPa)
N39028777: R5780.2 U125.F1(COMPb)
N39029145: C1665.1 R5785.1 R5787.2 U125.C1(FB)
N39047511: R5788.2 R6273.1 U125.B4(RUN)
N39047662: R5789.1 U30.K5(IO_3_K5/DIFFIO_TX_RX_B3N)
N39053590: R978.1 U125.E1(FREQ)

Not connected (* = marked no-connect by the designer): J15 3(TACH)*; U30 A2(IO_8_A2/DIFFIO_RX_T38P)* A5(IO_8)* A8(IO_8_A8/DIFFIO_RX_T27P)* A11(IO_8_A11/DIFFIO_RX_T29N)* A12(IO_6_A12/DIFFIO_RX_R34N)* B2(IO_8_B2/DIFFIO_RX_T38N)* B3(IO_8_B3/DIFFIO_RX_T35P)* B4(IO_8_B4/DIFFIO_RX_T35N)* B7(IO_8_B7/VREFB8N0)* B9(IO_8_B9/DEV_CLRN/DIFFIO_RX_T28N)* C9(IO_8_C9/CLK5N/DIFFIO_RX_T26N)* C10(IO_8_C10/CLK5P/DIFFIO_RX_T26P)* D6(IO_8_D6/CRC_ERROR/DIFFIO_RX_T34N)* D8(IO_8_D8/DEV_OE/DIFFIO_RX_T30P)* D11(IO_6_D11/DIFFIO_RX_R37N)* D13(IO_6_D13/VREFB6N0)* E13(IO_6_E13/CLK3N/DIFFIO_RX_R20N)* F4(IO_1B_F4/DIFFIO_RX_L14N)* F9(IO_6_F9/DPCLK3/DIFFIO_RX_R30P)* F10(IO_6_F10/DPCLK2/DIFFIO_RX_R30N)* F13(IO_6_F13/CLK3P/DIFFIO_RX_R20P)* G4(IO_1B_G4/DIFFIO_RX_L14P)* G5(IO_2_G5/CLK0N/DIFFIO_RX_L20N)* G10(IO_6_G10/CLK2N/DIFFIO_RX_R18N)* G12(IO_5_G12/DIFFIO_RX_R15N)* G13(IO_5_G13/DIFFIO_RX_R15P)* H1(IO_1B_H1/VREFB1N0)* H2(IO_1B_H2/DIFFIO_RX_L16N)* H3(IO_1B_H3/DIFFIO_RX_L16P)* H5(IO_2_H5/CLK1N/DIFFIO_RX_L22N)* H8(IO_5_H8/DIFFIO_RX_R14N)* H9(IO_5_H9/DIFFIO_RX_R14P)* H10(IO_5_H10/DIFFIO_RX_R12N)* H13(IO_5_H13/DIFFIO_RX_R13N)* J1(IO_2_J1/DIFFIO_RX_L21N)* J2(IO_2_J2/DIFFIO_RX_L21P)* J8(IO_3_J8/CLK7N/DIFFIO_TX_RX_B20N)* J9(IO_5_J9/DIFFIO_RX_R12P)* J10(IO_5_J10/RDN/DIFFIO_RX_R1N)* J12(IO_5_J12/DIFFIO_RX_R11N)* J13(IO_5_J13/DIFFIO_RX_R13P)* K1(IO_2_K1/DIFFIO_RX_L32N)* K2(IO_2_K2/DIFFIO_RX_L32P)* K7(IO_3_K7/DIFFIO_TX_RX_B15P)* K8(IO_3_K8/CLK7P/DIFFIO_TX_RX_B20P)* K10(IO_5_K10/RUP/DIFFIO_RX_R1P)* K13(IO_5_K13/VREFB5N0)* L1(IO_2_L1/VREFB2N0)* L2(IO_2)* L3(IO_2_L3/PLL_L_CLKOUTP/DIFFIO_RX_L31P)* L10(IO_3_L10/DIFFIO_TX_RX_B22P)* L11(IO_3_L11/CLK6P/DIFFIO_TX_RX_B18P)* L13(IO_5)* M1(IO_2_M1/DIFFIO_RX_L23N)* M2(IO_2_M2/DIFFIO_RX_L23P)* M3(IO_2_M3/PLL_L_CLKOUTN/DIFFIO_RX_L31N)* M10(IO_3_M10/DIFFIO_TX_RX_B22N)* M11(IO_3_M11/CLK6N/DIFFIO_TX_RX_B18N)* N2(IO_2_N2/DPCLK0/DIFFIO_RX_L24N)* N3(IO_2_N3/DPCLK1/DIFFIO_RX_L24P)* N10(IO_3_N10/DIFFIO_RX_B17N)* N11(IO_3_N11/VREFB3N0)*; U32 6(NC1)* 8(DXP5)* 9(DXN5)* 10(DXN6)* 11(DXP6)* 12(DXN7)* 13(DXP7)* 22(NC2)*; U125 D2(MODE/CLKIN)* F2(CLKOUT)* G5(PHMODE)*

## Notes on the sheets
sheet 44
- UBII-MAX10 2
- Bank 8: 3.3V IO
- Bank 5: 1.2V IO
- JTAG Master Selection:
  USB_DISABLEn = 0: External JTAG
  USB_DISABLEn = 1: On-Board UBII/PCIe EP Edge
       JTAG_INPUT_SOURCE = 0: PCIe EP edge
       JTAG_INPUT_SOURCE = 1: On-Board UBII
  JTAG Chain:
  SW4_2/3/4 = Low : Bypass
  SW4_2/3/4 = High: Enable
- Bank 6: 1.8V IO
- USB_MAX_JTAG = "1", Debug mode.
  EXT UBII is disabled on UBII MAX10.
- Bank 1A/1B: 3.3V IO
- Place R808~R810 near to U30
- Bank 2: 3.3V IO
- PLACE CLOSE MAX II PWR PIN
sheet 45
- PWR - VCCA_PLL
- VIN  : 12V
- VOUT : 1.2V
- ILOAD :8A
- RFB=60.4K x (0.5/Vout-0.5)
- FSW  : 500KHz
- Connect sense lines close to FPGA
- Vout = 1.2V
sheet 46
- MAX 10 PWR Manager 1
- I2C Address = b'1010000'
sheet 47
- MAX10 PWR Manager 2
- Core A
- Core C
- P TILE
- E TILE
- I2C ADDR = 4D
- Board Temp Sensor
